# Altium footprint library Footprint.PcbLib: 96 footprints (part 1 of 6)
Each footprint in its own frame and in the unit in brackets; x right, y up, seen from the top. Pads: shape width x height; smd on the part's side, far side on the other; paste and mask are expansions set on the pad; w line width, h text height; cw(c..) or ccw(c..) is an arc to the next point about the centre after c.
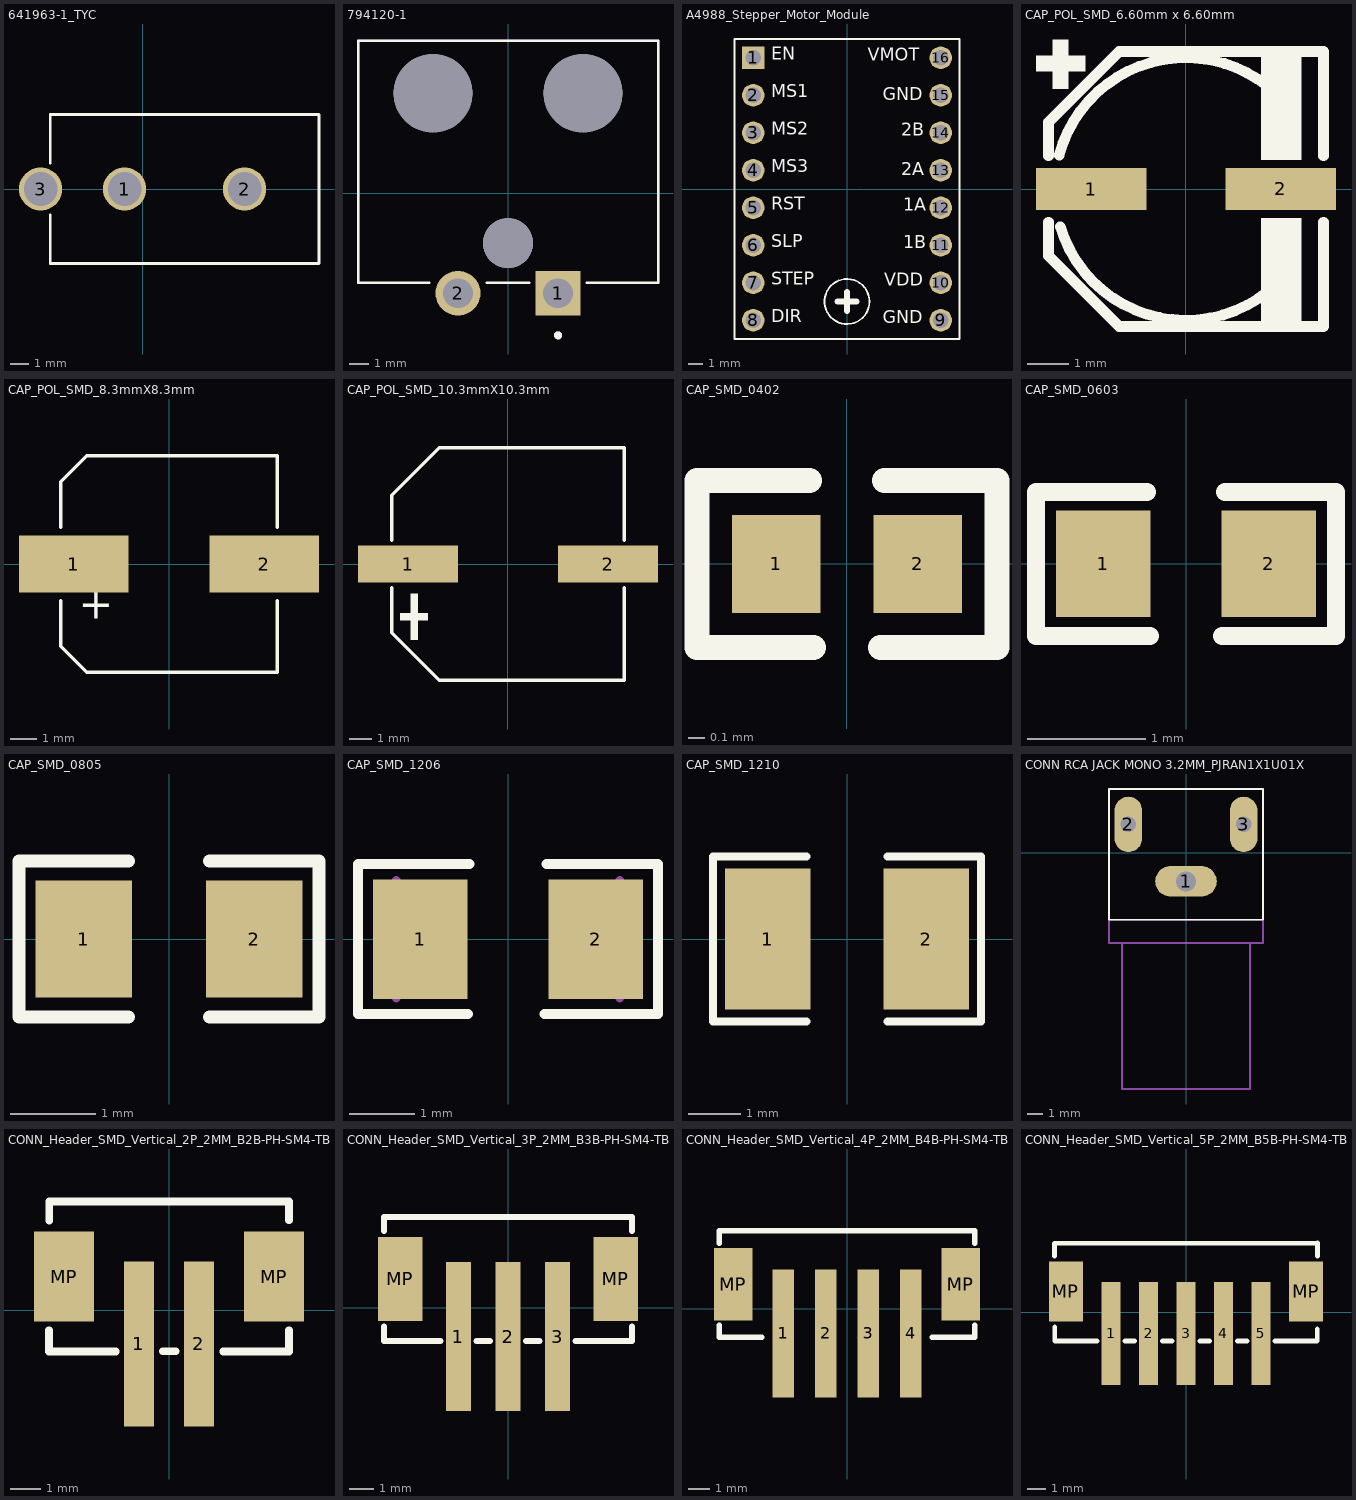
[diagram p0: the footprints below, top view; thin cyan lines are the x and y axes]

## 641963-1_TYC [mil]
pads (3):
  round 90 / inner round 60 / far side round 90 hole 70 paste-99999 mask+0: 1(-37.5,0) 2(212.5,0)
  round 90 / inner round 60 / far side round 90 hole 70 paste-99999 mask-45: 3(-212.5,0)
Top Overlay:
  lines w6: -192.5,-54.55 -192.5,-155 367.5,-155 367.5,155 -192.5,155 -192.5,54.55
Bottom Overlay:
  circle w20: c-217.5,0 r15
3D body "c-641963-1-k-3d.stp": height 586.18, standoff -137.32, extent -286.51,-196.06 463.48,153.94

## 794120-1 [mm]
pads (5):
  rect 2.28x2.28 hole 1.52: 1(2.54,-5.08)
  round 2.28 hole 1.52: 2(-2.54,-5.08)
  round 3.99 hole 3.99 unplated: ""(-3.81,5.08) ""(3.81,5.08)
  round 2.54 hole 2.54 unplated: ""(0,-2.54)
Top Overlay:
  circle w0.2: c2.54,-7.22 r0.1
  lines w0.127: -4,-4.54 -7.62,-4.54 -7.62,7.75 7.62,7.75 7.62,-4.54 4,-4.54 ; -1.08,-4.54 1.08,-4.54
Mechanical 13:
  circle w0.2: c2.54,-7.22 r0.1
  lines w0.127: -7.62,-4.54 -7.62,7.75 7.62,7.75 7.62,-4.54
3D body "794120-1.step": height 9.19, standoff -3.13, extent -7.62,-5.842 7.62,8.026

## A4988_Stepper_Motor_Module [mm]
pads (16):
  rect 1.53x1.53 hole 1.02: 1(-6.35,8.89)
  round 1.53 hole 1.02: 2(-6.35,6.35) 3(-6.35,3.81) 4(-6.35,1.27) 5(-6.35,-1.27) 6(-6.35,-3.81) 7(-6.35,-6.35) 8(-6.35,-8.89) 9(6.35,-8.89) 10(6.35,-6.35) 11(6.35,-3.81) 12(6.35,-1.27) 13(6.35,1.27) 14(6.35,3.81) 15(6.35,6.35) 16(6.35,8.89)
Top Overlay:
  lines w0.127: 1.524,-7.624 cw(c0,-7.622) 1.524,-7.62 ; -7.62,-10.16 7.62,-10.16 7.62,10.16 -7.62,10.16 -7.62,-10.16
  lines w0.406: -0.635,-7.62 0.635,-7.62 ; 0,-8.255 0,-6.985
  text "1A" at 3.81,-1.778 h1.5
  text "SLP" at -5.131,-4.242 h1.5
  text "GND" at 2.413,-9.398 h1.5
  text "VDD" at 2.54,-6.858 h1.5
  text "1B" at 3.81,-4.318 h1.5
  text "2A" at 3.683,0.635 h1.5
  text "2B" at 3.683,3.302 h1.5
  text "GND" at 2.413,5.715 h1.5
  text "VMOT" at 1.397,8.382 h1.5
  text "DIR" at -5.131,-9.322 h1.5
  text "STEP" at -5.131,-6.782 h1.5
  text "RST" at -5.131,-1.702 h1.5
  text "MS3" at -5.131,0.838 h1.5
  text "MS2" at -5.131,3.378 h1.5
  text "MS1" at -5.131,5.918 h1.5
  text "EN" at -5.131,8.458 h1.5
Mechanical 15:
  lines w0.003: 0.825,0.127 0.826,0.127
3D body "A4988 STEPPER MOTOR DRIVER CARRIER--3DModel-STEP-56544.STEP": height 6.09, standoff -5.79, extent -7.62,-10.16 7.62,10.16

## CAP_POL_SMD_6.60mm x 6.60mm [mm]
pads (2):
  rect 2.65x1 smd: 1(-2.275,0) 2(2.275,0)
Top Overlay:
  region: -2.818,2.4 -2.818,3.582 -3.2,3.582 -3.2,2.4
  rectangle: 1.8,-3.348 2.77,-0.7
  rectangle: 1.8,0.7 2.77,3.348
  rectangle: -3.6,2.818 -2.418,3.2
  lines w0.254: -3.3,-0.8 -3.3,-1.6 -1.6,-3.3 3.3,-3.3 3.3,-0.8 ; -3.3,0.8 -3.3,1.6 -1.6,3.3 3.3,3.3 3.3,0.8 ; -3.044,0.812 cw(c0,0) 2.397,2.044 ; -3.017,-0.905 ccw(c0,0) 2.41,-2.028
3D body "EEHZC1V470P.step": height 5.8, standoff 0, extent -3.65,-3.3 3.65,3.3

## CAP_POL_SMD_8.3mmX8.3mm [mm]
pads (2):
  rect 4.2x2.2 smd: 1(-3.65,0) 2(3.65,0)
Top Overlay:
  lines w0.127: -4.15,-1.413 -4.15,-3.15 -3.15,-4.15 4.15,-4.15 4.15,-1.413 ; -4.15,1.413 -4.15,3.15 -3.15,4.15 4.15,4.15 4.15,1.413
  text "+" at -3.454,-2.489 h2
3D body "A768KS227M1VLAE024.step": height 12.5, standoff 0, extent -4.761,-4.106 4.439,4.394

## CAP_POL_SMD_10.3mmX10.3mm [mm]
pads (2):
  rect 4.5x1.65 smd paste+0 mask+0.051: 1(-4.5,0) 2(4.5,0)
Top Overlay:
  region: -4.841,-2.214 -4.841,-2.523 -3.605,-2.523 -3.605,-2.214
  region: -4.378,-1.339 -4.378,-3.399 -4.068,-3.399 -4.068,-1.339
  lines w0.152: -5.226,-1.067 -5.226,-3.09 -3.09,-5.226 5.226,-5.226 5.226,-1.067 ; -5.226,1.067 -5.226,3.09 -3.09,5.226 5.226,5.226 5.226,1.067
3D body "CAP_PC_10X12P7_NCH.step": height 12.75, standoff 0, extent -5.601,-5.156 5.601,5.156

## CAP_SMD_0402 [mm]
pads (2):
  rect 0.54x0.6 smd: 1(-0.432,0) 2(0.432,0)
Top Overlay:
  lines w0.152: -0.914,-0.508 -0.914,0.508 -0.229,0.508 ; -0.889,-0.508 -0.203,-0.508 ; 0.203,-0.508 0.889,-0.508 ; 0.229,0.508 0.914,0.508 0.914,-0.508
3D body "0402YA470JAT2A.STEP": height 0.56, standoff 0, extent -0.5,-0.25 0.5,0.25

## CAP_SMD_0603 [mm]
pads (2):
  rect 0.8x0.9 smd paste+0 mask+0.051: 1(-0.7,0) 2(0.7,0)
Top Overlay:
  lines w0.152: -0.33,0.608 -1.27,0.608 -1.27,-0.611 -0.305,-0.611 ; 0.305,-0.611 1.27,-0.611 1.27,0.608 0.33,0.608
3D body "CGA3E2X7R1H222K080AD.step": height 0.95, standoff 0, extent -0.8,-0.4 0.8,0.4

## CAP_SMD_0805 [mm]
pads (2):
  rect 1.133x1.377 smd paste-100 mask+0.051: 1(-1,0) 2(1,0)
Top Overlay:
  lines w0.152: -0.476,-0.917 -1.761,-0.917 -1.761,0.917 -0.476,0.917 ; 0.476,-0.917 1.761,-0.917 1.761,0.917 0.476,0.917
3D body "C0805C103K1RACTU.step": height 0.88, standoff 0, extent -1.1,-0.737 1.1,0.713

## CAP_SMD_1206 [mm]
pads (2):
  rect 1.44x1.82 smd: 1(-1.336,0) 2(1.336,0)
Top Overlay:
  lines w0.152: -0.61,-1.143 -2.284,-1.143 -2.284,1.147 -0.584,1.147 ; 0.559,-1.143 2.284,-1.143 2.284,1.147 0.584,1.147
Mechanical 13:
  lines w0.127: -1.7,-0.9 -1.7,0.9 ; 1.7,-0.9 1.7,0.9
3D body "step_temp.STEP": height 1.8, standoff 0, extent -1.6,-0.8 1.6,0.8

## CAP_SMD_1210 [mm]
pads (2):
  rect 1.635x2.7 smd paste-100 mask+0.051: 1(-1.517,0) 2(1.517,0)
Top Overlay:
  lines w0.152: -0.776,-1.579 -2.564,-1.579 -2.564,1.579 -0.776,1.579 ; 0.776,-1.579 2.564,-1.579 2.564,1.579 0.776,1.579
3D body "CAP1210.STEP": height 1.5, standoff 0, extent -1.749,-1.3 1.651,1.3

## CONN RCA JACK MONO 3.2MM_PJRAN1X1U01X [mm]
pads (3):
  oval 4x2 hole 1.3 square: 1(0,-1.85)
  oval 1.8x3.6 hole 1 square: 2(-3.75,1.85) 3(3.75,1.85)
Top Overlay:
  lines w0.127: -5,-4.35 5,-4.35 5,4.15 -5,4.15 -5,-4.35
Mechanical 13:
  lines w0.127: -5,-4.35 -5,-5.85 -4.15,-5.85 ; -5,-4.35 5,-4.35 ; -5,-4.35 -5,4.15 5,4.15 5,-4.35 ; -4.15,-5.85 -4.15,-15.35 4.15,-15.35 4.15,-5.85 ; -4.15,-5.85 4.15,-5.85 ; 4.15,-5.85 5,-5.85 5,-4.35
  text "PCB EDGE" at -3.75,-4.22 h1.02
3D body "PJRAN1X1U01X.step": height 12, standoff -5.02, extent -5.029,-15.875 4.978,3.632

## CONN_Header_SMD_Vertical_2P_2MM_B2B-PH-SM4-TB [mm]
pads (4):
  rect 1x5.5 smd paste+0 mask+0.051: 1(-1,-1.125) 2(1,-1.125)
  rect 2x3 smd paste+0 mask+0.051: MP(-3.5,1.125) MP(3.5,1.125)
Top Overlay:
  lines w0.254: -4,-0.66 -4,-1.375 -1.778,-1.375 ; -3.988,2.979 -3.988,3.625 4,3.625 4,2.997 ; -0.203,-1.372 0.229,-1.372 ; 1.803,-1.375 4,-1.375 4,-0.66
3D body "B2B-PH-SM4-TB.STEP": height 6.75, standoff 0, extent -4.038,-3.348 3.912,3.652

## CONN_Header_SMD_Vertical_3P_2MM_B3B-PH-SM4-TB [mm]
pads (5):
  rect 1x6 smd paste+0 mask+0.051: 1(-2,-1.163) 2(0,-1.163) 3(2,-1.163)
  rect 1.8x3.4 smd paste+0 mask+0.051: MP(-4.35,1.163) MP(4.35,1.163)
Top Overlay:
  lines w0.254: -5,-0.769 -5,-1.338 -2.731,-1.338 ; -5,3.094 -5,3.663 5,3.663 ; -1.269,-1.338 -0.731,-1.338 ; 0.731,-1.338 1.269,-1.338 ; 2.731,-1.338 5.001,-1.338 5.001,-0.769 ; 5.001,3.094 5.001,3.663
3D body "B3B-PH-SM4-TB.STEP": height 6.8, standoff 0.05, extent -4.978,-3.596 4.972,3.404

## CONN_Header_SMD_Vertical_4P_2MM_B4B-PH-SM4-TB [mm]
pads (6):
  rect 1x6 smd paste+0 mask+0.051: 1(-2.997,-1.158) 2(-0.997,-1.158) 3(1.003,-1.158) 4(3.001,-1.158)
  rect 1.8x3.4 smd paste+0 mask+0.051: MP(-5.349,1.158) MP(5.349,1.158)
Top Overlay:
  lines w0.254: -6,-0.773 -6,-1.332 -3.999,-1.332 ; -6,3.089 -6,3.668 ; -5.999,3.668 6.001,3.668 6.001,3.089 ; 4,-1.332 6.001,-1.332 6.001,-0.773
3D body "B4B-PH-SM4-TB.STEP": height 6.75, standoff 0, extent -5.924,-3.484 6.026,3.516

## CONN_Header_SMD_Vertical_5P_2MM_B5B-PH-SM4-TB [mm]
pads (7):
  rect 1x5.5 smd paste+0 mask+0.051: 1(-4,-1.125) 2(-2,-1.125) 3(0,-1.125) 4(2,-1.125) 5(4,-1.125)
  rect 1.8x3.2 smd paste+0 mask+0.051: MP(-6.4,1.125) MP(6.4,1.125)
Top Overlay:
  lines w0.254: -7.01,2.997 -7.01,3.675 7.01,3.7 7.01,3.005 ; -7,-0.787 -7,-1.525 -4.731,-1.525 ; -3.269,-1.525 -2.731,-1.525 ; -1.269,-1.525 -0.731,-1.525 ; 0.731,-1.525 1.269,-1.525 ; 2.731,-1.525 3.269,-1.525 ; 5.269,-1.525 4.731,-1.525 7,-1.525 7,-0.889
3D body "B5B-PH-SM4-TB.STEP": height 6.75, standoff 0, extent -6.95,-3.763 7,3.237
